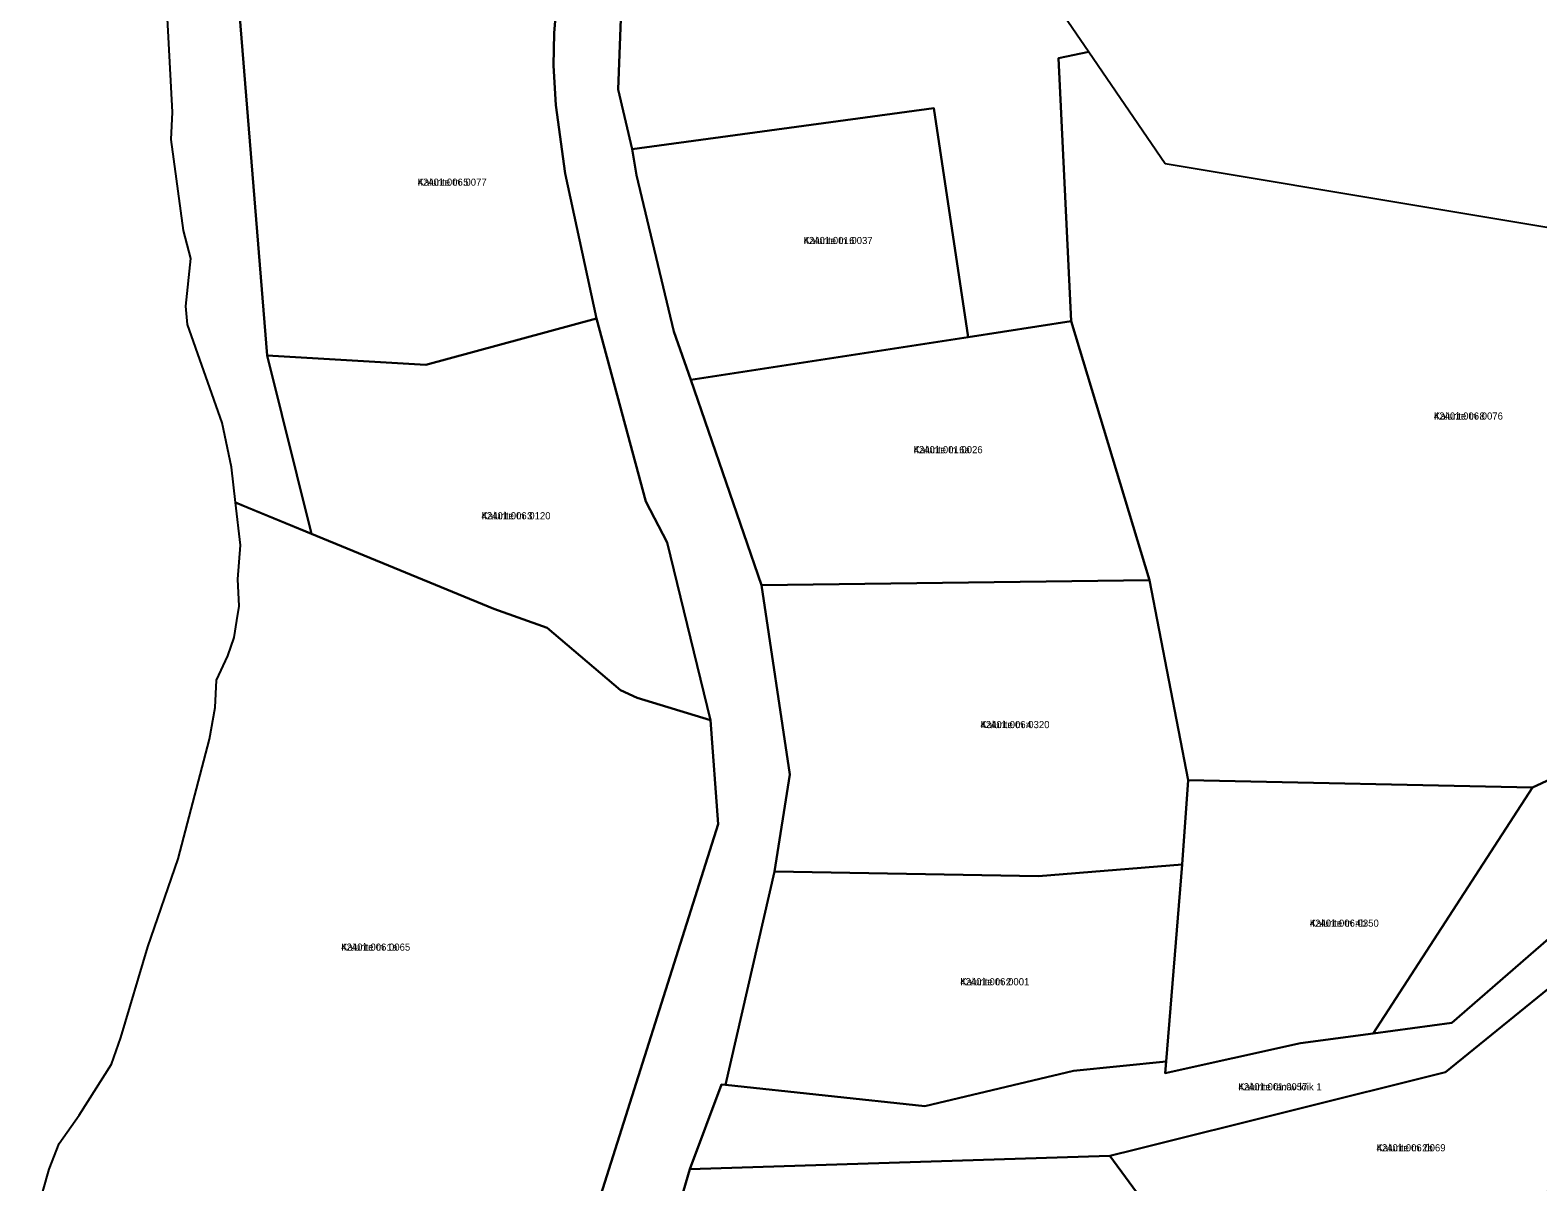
# Model space of a CAD drawing. Extents: x 595979 to 597983, y 6604231 to 6607350.
# Drawn here: x 596325.9 to 596642.6, y 6606884.7 to 6607126.6 of the extents above; entities that cross this region are included whole.
import ezdxf

# ---------------------------------------------------------------- set-up
doc = ezdxf.new("R2010")
doc.units = 0
for name, color, linetype in [('L_AADRESS', 7, 'Continuous'), ('PIIR', 7, 'Continuous'), ('TUNNUS', 7, 'Continuous')]:
    doc.layers.add(name, color=color, linetype=linetype)

msp = doc.modelspace()

# ---------------------------------------------------------------- linework, layer by layer
at = {"layer": 'PIIR'}
for points in [[(596489.35, 6607208.1), (596548.29, 6607122.04), (596541.96, 6607120.71), (596544.58, 6607065.45), (596522.96, 6607062.1), (596515.74, 6607110.18), (596452.37, 6607101.57), (596449.44, 6607114.1), (596450.12, 6607132.65), (596453.22, 6607146.91), (596459.97, 6607162.74)], [(596369.69, 6607131.86), (596436.42, 6607131.12), (596435.98, 6607125.93), (596435.8, 6607119.13), (596436.34, 6607110.82), (596438.26, 6607096.51), (596444.88, 6607066.02), (596408.99, 6607056.28), (596375.64, 6607058.29)], [(596564.33, 6607098.59), (596781.71, 6607062.3), (596690.42, 6607052.21), (596693.12, 6606991.47), (596641.52, 6606967.57), (596569.14, 6606969.05), (596561.08, 6607011.06), (596544.58, 6607065.45), (596541.96, 6607120.71), (596548.29, 6607122.04)], [(596522.96, 6607062.1), (596464.7, 6607053.15), (596461.13, 6607063.3), (596453.27, 6607096.14), (596452.37, 6607101.57), (596515.74, 6607110.18)], [(596444.88, 6607066.02), (596455.26, 6607027.59), (596459.72, 6607019.01), (596468.81, 6606981.7), (596453.44, 6606986.37), (596449.94, 6606987.98), (596434.5, 6607001.09), (596423.31, 6607005.07), (596384.98, 6607020.82), (596375.64, 6607058.29), (596408.99, 6607056.28)], [(596479.51, 6607010.01), (596464.7, 6607053.15), (596522.96, 6607062.1), (596544.58, 6607065.45), (596561.08, 6607011.06)], [(596561.08, 6607011.06), (596569.14, 6606969.05), (596567.93, 6606951.39), (596537.72, 6606948.94), (596482.25, 6606949.87), (596485.51, 6606970.3), (596479.51, 6607010.01)], [(596641.52, 6606967.57), (596693.12, 6606991.47), (596693.63, 6606980.36), (596694.59, 6606962.36), (596648.1, 6606938.58), (596624.57, 6606918.1), (596608.07, 6606915.86)], [(596569.14, 6606969.05), (596641.52, 6606967.57), (596608.07, 6606915.86), (596592.79, 6606913.83), (596564.33, 6606907.55), (596564.52, 6606909.98), (596567.93, 6606951.39)], [(596548.26, 6606890.04), (596464.47, 6606887.4), (596471.1, 6606905.17), (596471.94, 6606905.07), (596513.82, 6606900.6), (596545.11, 6606908.01), (596564.52, 6606909.98), (596564.33, 6606907.55), (596592.79, 6606913.83), (596608.07, 6606915.86), (596624.57, 6606918.1), (596648.1, 6606938.58), (596694.59, 6606962.36), (596694.97, 6606954.79), (596677.69, 6606947.28), (596659.33, 6606937.04), (596623.21, 6606907.76), (596558.1, 6606891.54), (596552.73, 6606890.18)], [(596552.73, 6606890.18), (596558.1, 6606891.54), (596623.21, 6606907.76), (596659.33, 6606937.04), (596677.69, 6606947.28), (596694.97, 6606954.79), (596697.35, 6606910.02), (596631, 6606875.52), (596634.38, 6606847.12), (596631.03, 6606832.78), (596620.92, 6606827.47), (596596.63, 6606830.4)], [(596471.94, 6606905.07), (596482.25, 6606949.87), (596537.72, 6606948.94), (596567.93, 6606951.39), (596564.52, 6606909.98), (596545.11, 6606908.01), (596513.82, 6606900.6)], [(596464.47, 6606887.4), (596548.26, 6606890.04), (596552.73, 6606890.18), (596596.63, 6606830.4), (596593.56, 6606828.51), (596530.45, 6606789.96), (596501.66, 6606797.02), (596452.89, 6606809.63), (596451.96, 6606809.89), (596452.59, 6606835.16), (596457.38, 6606863.19)]]:
    msp.add_lwpolyline(points, close=True, dxfattribs=at)
for points in [[(596450.12, 6607132.65), (596449.44, 6607114.1), (596452.37, 6607101.57), (596453.27, 6607096.14), (596461.13, 6607063.3), (596464.7, 6607053.15), (596479.51, 6607010.01), (596485.51, 6606970.3), (596482.25, 6606949.87), (596471.94, 6606905.07), (596471.1, 6606905.17), (596464.47, 6606887.4), (596457.38, 6606863.19)], [(596369.69, 6607131.86), (596375.64, 6607058.29), (596384.98, 6607020.82), (596371.65, 6607026.29), (596369.04, 6607027.36), (596368.18, 6607034.82), (596366.23, 6607044.12), (596358.95, 6607064.76), (596358.56, 6607068.6), (596359.61, 6607078.65), (596358.08, 6607084.53), (596355.53, 6607103.63), (596355.78, 6607109.34), (596354.72, 6607129.05)], [(596442.64, 6606872.04), (596470.43, 6606959.84), (596468.81, 6606981.7), (596459.72, 6607019.01), (596455.26, 6607027.59), (596444.88, 6607066.02), (596438.26, 6607096.51), (596436.34, 6607110.82), (596435.8, 6607119.13), (596435.98, 6607125.93), (596436.42, 6607131.12)], [(596325.88, 6606873.33), (596329.85, 6606887.36), (596332.01, 6606892.81), (596336.2, 6606898.73), (596342.95, 6606909.45), (596344.93, 6606915.01), (596350.62, 6606934.06), (596356.97, 6606952.58), (596363.58, 6606977.71), (596364.77, 6606984.33), (596365, 6606990.07), (596367.38, 6606995.22), (596368.74, 6606999.01), (596369.32, 6607002.6), (596369.8, 6607005.63), (596369.54, 6607011.32), (596370.06, 6607018.46), (596369.04, 6607027.36), (596384.98, 6607020.82), (596423.31, 6607005.07), (596434.5, 6607001.09), (596449.94, 6606987.98), (596453.44, 6606986.37), (596468.81, 6606981.7), (596470.43, 6606959.84), (596442.64, 6606872.04)]]:
    msp.add_lwpolyline(points, dxfattribs=at)

# ---------------------------------------------------------------- texts
at = {"layer": 'L_AADRESS'}
for s, p in [('Kalurite tn 5', (596407.29, 6607093.91)), ('Kalurite tn 6', (596488.38, 6607081.66)), ('Kalurite tn 8', (596620.8, 6607044.8)), ('Kalurite tn 6a', (596511.49, 6607037.73)), ('Kalurite tn 3', (596420.71, 6607023.86)), ('Kalurite tn 4', (596525.54, 6606980)), ('Kalurite tn 4b', (596594.72, 6606938.3)), ('Kalurite tn 1a', (596391.23, 6606933.27)), ('Kalurite tn 2', (596521.3, 6606926)), ('Kalurite tänav lõik 1', (596579.72, 6606903.94)), ('Kalurite tn 2b', (596608.75, 6606891.13))]:
    msp.add_text(s, height=1.5, dxfattribs=at).set_placement(p)
at = {"layer": 'TUNNUS'}
for s, p in [('42401:006:0077', (596407.29, 6607093.91)), ('42401:001:0037', (596488.38, 6607081.66)), ('42401:006:0076', (596620.8, 6607044.8)), ('42401:001:0026', (596511.49, 6607037.73)), ('42401:006:0120', (596420.71, 6607023.86)), ('42401:006:0320', (596525.54, 6606980)), ('42401:006:0350', (596594.72, 6606938.3)), ('42401:006:0065', (596391.23, 6606933.27)), ('42401:006:0001', (596521.3, 6606926)), ('42401:001:0057', (596579.72, 6606903.94)), ('42401:006:0069', (596608.75, 6606891.13))]:
    msp.add_text(s, height=1.5, dxfattribs=at).set_placement(p)

doc.saveas('drawing.dxf')
